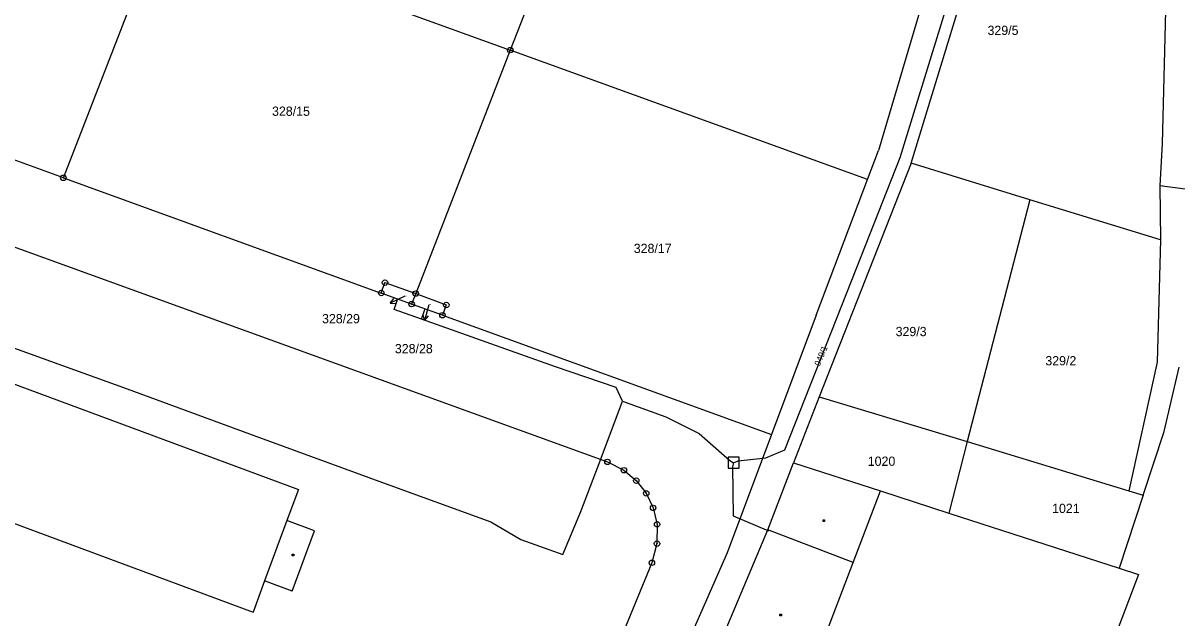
# Model space of a CAD drawing. Extents: x -770973 to -770265, y -1049936 to -1049427.
# Drawn here: x -770637.6 to -770531.6, y -1049786.5 to -1049731.9 of the extents above; entities that cross this region are included whole.
import ezdxf

# ---------------------------------------------------------------- set-up
doc = ezdxf.new("R2010")
doc.units = 0
for name, color, linetype in [('Vrstva 1', 7, 'Continuous'), ('Vrstva 14', 7, 'Continuous'), ('Vrstva 16', 7, 'Continuous'), ('Vrstva 2', 7, 'Continuous'), ('Vrstva 25', 7, 'Continuous'), ('Vrstva 28', 7, 'Continuous'), ('Vrstva 50', 7, 'Continuous')]:
    doc.layers.add(name, color=color, linetype=linetype)

msp = doc.modelspace()

# ---------------------------------------------------------------- linework, layer by layer
at = {"layer": 'Vrstva 1'}
for p, q in [((-770583.79, -1049711.08), (-770592.84, -1049734.39)), ((-770532.33, -1049718.02), (-770532.95, -1049742.96)), ((-770633.88, -1049746.11), (-770624.83, -1049722.81)), ((-770624.83, -1049722.81), (-770592.84, -1049734.39)), ((-770552.69, -1049722.34), (-770559.02, -1049743.61)), ((-770556.01, -1049744.77), (-770549.48, -1049723.46)), ((-770696.95, -1049731.26), (-770583.91, -1049772.18)), ((-770592.84, -1049734.39), (-770601.52, -1049756.73)), ((-770560.03, -1049746.27), (-770592.84, -1049734.39)), ((-770633.88, -1049746.11), (-770663.04, -1049735.56)), ((-770532.95, -1049742.96), (-770533.16, -1049746.85)), ((-770560.03, -1049746.27), (-770559.02, -1049743.61)), ((-770556.01, -1049744.77), (-770564.45, -1049766.21)), ((-770545.12, -1049748.12), (-770556.01, -1049744.77)), ((-770633.88, -1049746.11), (-770604.68, -1049756.68)), ((-770564.73, -1049758.71), (-770560.03, -1049746.27)), ((-770527.6, -1049747.6), (-770533.16, -1049746.85)), ((-770533.16, -1049746.85), (-770533.12, -1049751.81)), ((-770545.12, -1049748.12), (-770550.87, -1049770.32)), ((-770533.12, -1049751.81), (-770545.12, -1049748.12)), ((-770533.12, -1049751.81), (-770533.43, -1049763.02)), ((-770604.68, -1049756.68), (-770604.34, -1049755.73)), ((-770604.34, -1049755.73), (-770601.52, -1049756.73)), ((-770601.89, -1049757.7), (-770604.68, -1049756.68)), ((-770601.52, -1049756.73), (-770601.89, -1049757.7)), ((-770601.52, -1049756.73), (-770598.71, -1049757.78)), ((-770599.06, -1049758.72), (-770601.89, -1049757.7)), ((-770598.71, -1049757.78), (-770599.06, -1049758.72)), ((-770599.06, -1049758.72), (-770568.84, -1049769.66)), ((-770564.73, -1049758.71), (-770568.84, -1049769.66)), ((-770652.37, -1049759.85), (-770612.28, -1049774.71)), ((-770533.43, -1049763.02), (-770536.03, -1049774.82)), ((-770532.79, -1049769.4), (-770531.39, -1049763.49)), ((-770564.45, -1049766.21), (-770566.83, -1049772.25)), ((-770564.45, -1049766.21), (-770550.87, -1049770.32)), ((-770568.84, -1049769.66), (-770572.91, -1049780.51)), ((-770534.71, -1049775.22), (-770532.79, -1049769.4)), ((-770550.87, -1049770.32), (-770552.56, -1049776.87)), ((-770550.87, -1049770.32), (-770536.03, -1049774.82)), ((-770655.08, -1049771.64), (-770616.45, -1049785.96)), ((-770583.91, -1049772.18), (-770582.4, -1049772.94)), ((-770569.18, -1049778.4), (-770566.83, -1049772.25)), ((-770566.83, -1049772.25), (-770558.84, -1049774.84)), ((-770582.4, -1049772.94), (-770581.26, -1049773.9)), ((-770581.26, -1049773.9), (-770580.35, -1049775.06)), ((-770612.28, -1049774.71), (-770613.34, -1049777.57)), ((-770558.84, -1049774.84), (-770552.56, -1049776.87)), ((-770536.03, -1049774.82), (-770534.71, -1049775.22)), ((-770580.35, -1049775.06), (-770579.71, -1049776.4)), ((-770534.71, -1049775.22), (-770536.92, -1049781.92)), ((-770579.71, -1049776.4), (-770579.35, -1049777.91)), ((-770552.56, -1049776.87), (-770536.92, -1049781.92)), ((-770610.81, -1049778.51), (-770613.34, -1049777.57)), ((-770579.35, -1049777.91), (-770579.36, -1049779.68)), ((-770612.86, -1049784.04), (-770610.81, -1049778.51)), ((-770574.55, -1049791.16), (-770569.18, -1049778.4)), ((-770579.36, -1049779.68), (-770579.83, -1049781.44)), ((-770572.91, -1049780.51), (-770582.76, -1049802.9)), ((-770579.83, -1049781.44), (-770587.66, -1049800.38)), ((-770536.92, -1049781.92), (-770535.14, -1049782.5)), ((-770615.39, -1049783.1), (-770616.45, -1049785.96)), ((-770612.86, -1049784.04), (-770615.39, -1049783.1)), ((-770535.14, -1049782.5), (-770538.43, -1049791.15))]:
    msp.add_line(p, q, dxfattribs=at)
at = {"layer": 'Vrstva 16'}
for p, q in [((-770602.51, -1049756.97), (-770603.86, -1049757.62)), ((-770603.86, -1049757.62), (-770603.52, -1049757.18)), ((-770603.86, -1049757.62), (-770603.3, -1049757.63)), ((-770600.31, -1049757.75), (-770600.72, -1049759.19)), ((-770600.72, -1049759.19), (-770600.82, -1049758.64)), ((-770600.72, -1049759.19), (-770600.34, -1049758.78))]:
    msp.add_line(p, q, dxfattribs=at)
at = {"layer": 'Vrstva 2'}
for p, q in [((-770561.35, -1049781.4), (-770558.84, -1049774.84)), ((-770613.34, -1049777.57), (-770615.39, -1049783.1)), ((-770561.35, -1049781.4), (-770569.18, -1049778.4)), ((-770566.12, -1049793.88), (-770561.35, -1049781.4))]:
    msp.add_line(p, q, dxfattribs=at)
at = {"layer": 'Vrstva 25'}
for p, q in [((-770564.11, -1049777.5), (-770563.96, -1049777.5)), ((-770564.11, -1049777.65), (-770564.11, -1049777.5)), ((-770563.96, -1049777.65), (-770564.11, -1049777.65)), ((-770563.96, -1049777.5), (-770563.96, -1049777.65)), ((-770612.86, -1049780.64), (-770612.71, -1049780.64)), ((-770612.86, -1049780.79), (-770612.86, -1049780.64)), ((-770612.71, -1049780.79), (-770612.86, -1049780.79)), ((-770612.71, -1049780.64), (-770612.71, -1049780.79)), ((-770568.07, -1049786.14), (-770567.92, -1049786.14)), ((-770568.07, -1049786.29), (-770568.07, -1049786.14)), ((-770567.92, -1049786.29), (-770568.07, -1049786.29)), ((-770567.92, -1049786.14), (-770567.92, -1049786.29))]:
    msp.add_line(p, q, dxfattribs=at)
at = {"layer": 'Vrstva 28'}
for centre, radius in [((-770592.84, -1049734.39), 0.25), ((-770592.84, -1049734.39), 0.005), ((-770633.88, -1049746.11), 0.25), ((-770633.88, -1049746.11), 0.005), ((-770604.34, -1049755.73), 0.25), ((-770604.34, -1049755.73), 0.005), ((-770604.68, -1049756.68), 0.25), ((-770604.68, -1049756.68), 0.005), ((-770601.52, -1049756.73), 0.25), ((-770601.52, -1049756.73), 0.005), ((-770601.89, -1049757.7), 0.25), ((-770601.89, -1049757.7), 0.005), ((-770598.71, -1049757.78), 0.25), ((-770598.71, -1049757.78), 0.005), ((-770599.06, -1049758.72), 0.25), ((-770599.06, -1049758.72), 0.005), ((-770583.91, -1049772.18), 0.25), ((-770583.91, -1049772.18), 0.005), ((-770582.4, -1049772.94), 0.25), ((-770582.4, -1049772.94), 0.005), ((-770581.26, -1049773.9), 0.25), ((-770581.26, -1049773.9), 0.005), ((-770580.35, -1049775.06), 0.25), ((-770580.35, -1049775.06), 0.005), ((-770579.71, -1049776.4), 0.25), ((-770579.71, -1049776.4), 0.005), ((-770579.35, -1049777.91), 0.25), ((-770579.35, -1049777.91), 0.005), ((-770579.36, -1049779.68), 0.25), ((-770579.36, -1049779.68), 0.005), ((-770579.83, -1049781.44), 0.25), ((-770579.83, -1049781.44), 0.005)]:
    msp.add_circle(centre, radius, dxfattribs=at)
at = {"layer": 'Vrstva 50'}
for p, q in [((-770553.27, -1049732.05), (-770550.55, -1049723.17)), ((-770557.02, -1049744.24), (-770553.27, -1049732.05)), ((-770561.01, -1049754.34), (-770557.02, -1049744.24)), ((-770567.61, -1049771.06), (-770561.01, -1049754.34)), ((-770603.49, -1049758.18), (-770603.15, -1049757.19)), ((-770601, -1049759.07), (-770603.49, -1049758.18)), ((-770601, -1049759.07), (-770600.64, -1049758.11)), ((-770588.67, -1049763.44), (-770601, -1049759.07)), ((-770640.4, -1049761.04), (-770628.02, -1049765.48)), ((-770583.1, -1049765.35), (-770588.67, -1049763.44)), ((-770628.02, -1049765.48), (-770616.19, -1049769.82)), ((-770582.53, -1049766.6), (-770583.1, -1049765.35)), ((-770584.57, -1049772.09), (-770582.53, -1049766.6)), ((-770582.53, -1049766.6), (-770578.56, -1049768.04)), ((-770578.56, -1049768.04), (-770575.47, -1049769.58)), ((-770575.47, -1049769.58), (-770572.66, -1049772.06)), ((-770616.19, -1049769.82), (-770604.58, -1049774.08)), ((-770571.82, -1049771.75), (-770572.82, -1049771.75)), ((-770572.82, -1049771.75), (-770572.82, -1049772.75)), ((-770571.9, -1049772.08), (-770569.35, -1049771.82)), ((-770571.82, -1049772.75), (-770571.82, -1049771.75)), ((-770569.35, -1049771.82), (-770567.61, -1049771.06)), ((-770586.34, -1049776.74), (-770584.57, -1049772.09)), ((-770572.82, -1049772.75), (-770571.82, -1049772.75)), ((-770572.66, -1049772.06), (-770572.32, -1049772.25)), ((-770572.32, -1049772.25), (-770572.43, -1049772.62)), ((-770572.43, -1049772.62), (-770572.36, -1049777.13)), ((-770572.32, -1049772.25), (-770571.9, -1049772.08)), ((-770604.58, -1049774.08), (-770594.62, -1049777.67)), ((-770587.99, -1049780.69), (-770586.34, -1049776.74)), ((-770572.36, -1049777.13), (-770569.11, -1049778.49)), ((-770594.62, -1049777.67), (-770591.85, -1049779.31)), ((-770591.85, -1049779.31), (-770587.99, -1049780.69))]:
    msp.add_line(p, q, dxfattribs=at)

# ---------------------------------------------------------------- texts
at = {"layer": 'Vrstva 14'}
for s, height, p in [('329/5', 0.85, (-770549, -1049733)), ('328/15', 0.85, (-770614.71, -1049740.42)), ('328/17', 0.85, (-770581.49, -1049753.01)), ('328/29', 0.05, (-770602.51, -1049756.97)), ('328/28', 0.05, (-770600.31, -1049757.75)), ('329/3', 0.85, (-770557.44, -1049760.64)), ('329/2', 0.85, (-770543.69, -1049763.32)), ('1020', 0.85, (-770560, -1049772.54)), ('1021', 0.85, (-770543.07, -1049776.87))]:
    msp.add_text(s, height=height, dxfattribs=at).set_placement(p)
msp.add_text('949/1', height=0.57, rotation=67.4428, dxfattribs=at).set_placement((-770564.4, -1049763.43))
at = {"layer": 'Vrstva 16'}
for s, p in [('328/29', (-770610.12, -1049759.46)), ('328/28', (-770603.43, -1049762.21))]:
    msp.add_text(s, height=0.85, dxfattribs=at).set_placement(p)

doc.saveas('drawing.dxf')
